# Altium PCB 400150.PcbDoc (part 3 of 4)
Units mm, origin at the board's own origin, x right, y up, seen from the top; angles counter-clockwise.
Board outline 101.6 x 63.5 mm, 4 copper layers (Top Layer, Mid-Layer 1, Mid-Layer 2, Bottom Layer), stack 1.582 mm thick; 248 components, 179 nets, 1093 pads, 875 vias.
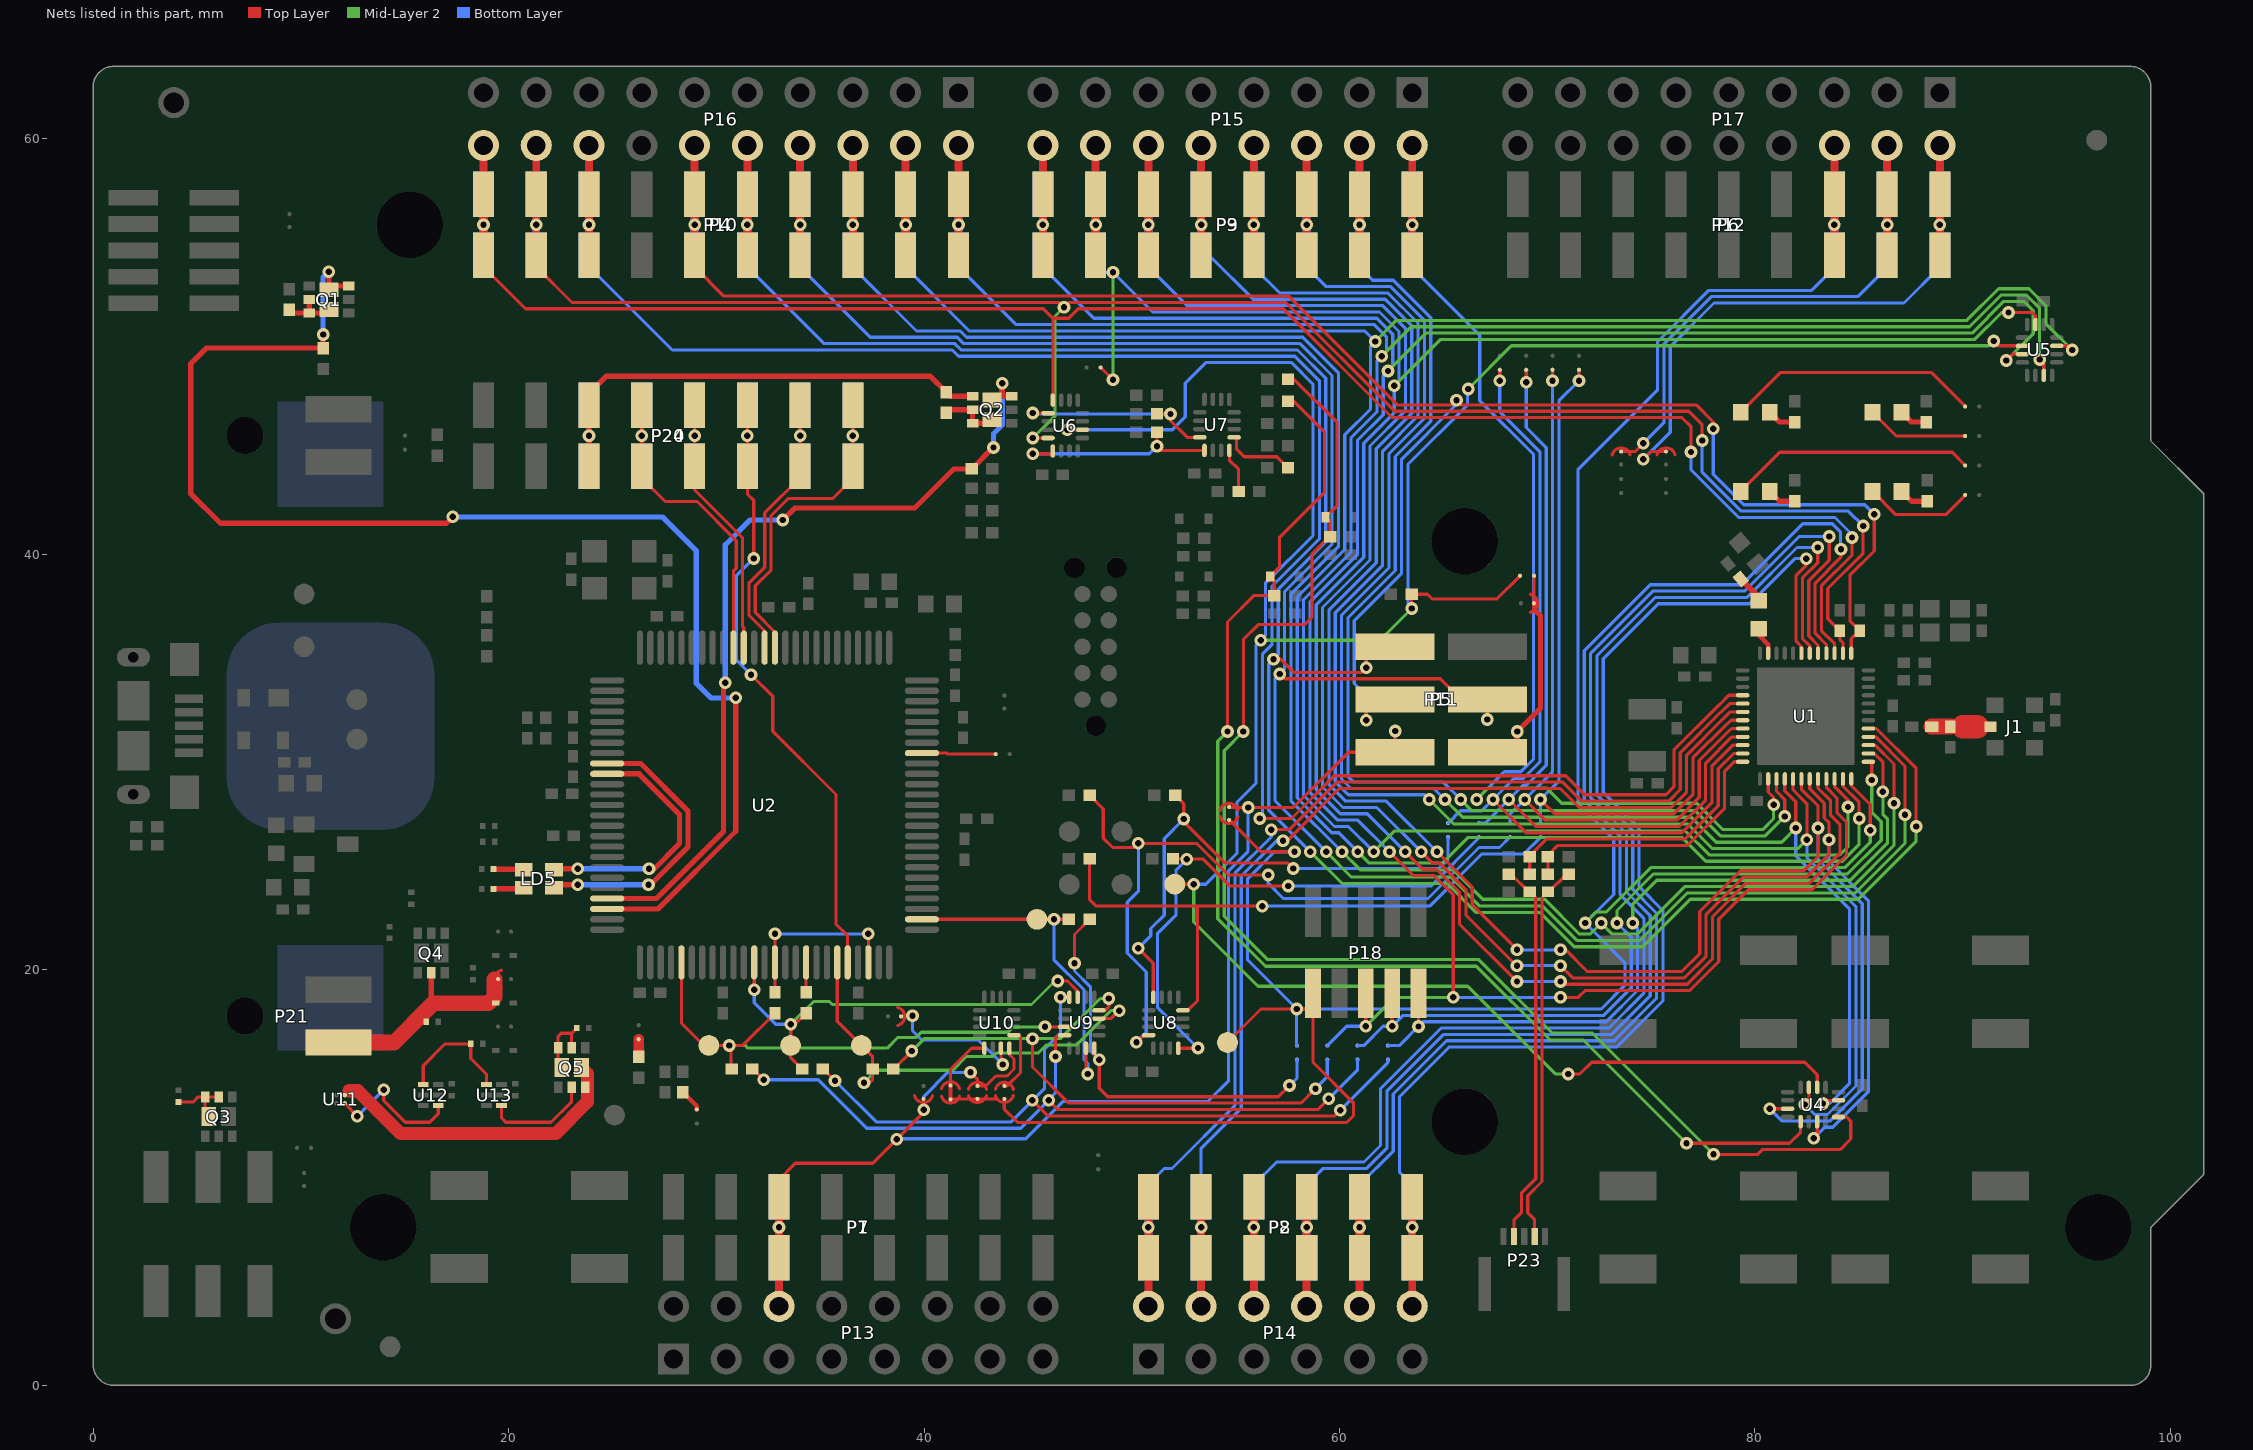
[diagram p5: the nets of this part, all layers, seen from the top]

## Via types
v1: diameter 0.61, hole 0.305, Top Layer to Bottom Layer, tented both sides, 836 vias
v2: diameter 0.61, hole 0.305, Top Layer to Bottom Layer, 23 vias
v3: diameter 0.66, hole 0.33, Top Layer to Bottom Layer, tented both sides, 16 vias

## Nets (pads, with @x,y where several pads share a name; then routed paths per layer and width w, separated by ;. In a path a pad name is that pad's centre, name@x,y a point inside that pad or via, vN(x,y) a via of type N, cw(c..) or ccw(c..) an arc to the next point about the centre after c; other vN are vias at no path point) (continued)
NetD5_1: D5.1 R35.1 R42.2 U4.9 | length 61.9
  Top Layer w0.152: v1(54.61,31.471) 54.61,36.742 55.879,38.01 R42.2@56.861,38.01 56.861,38.732 D5.1@56.661,38.932 57.107,39.378 57.107,40.8 59.274,42.967 59.274,45.891 57.804,47.361 R35.1@57.521,47.361 ; v1(76.705,11.65) 76.706,11.649 81.661,11.649 82.195,12.183 U4.9@82.195,12.688
  Mid-Layer 2 w0.152: v1(54.61,31.471) 54.143,31.004 54.143,22.458 56.436,20.165 66.589,20.165 70.137,16.618 71.739,16.618 v1(76.705,11.65) v1(76.705,11.65)
NetD6_1: D6.1 R36.1 R43.2 U4.13 | length 67.4
  Top Layer w0.152: v1(55.372,31.471) 55.372,35.897 56.089,36.613 58.313,36.613 58.682,36.982 58.682,40.03 R43.2@59.469,40.818 ; R36.1@57.521,48.428 57.804,48.428 59.884,46.348 59.884,42.339 D6.1@59.328,41.783 59.548,41.563 R43.2@59.548,40.835 ; v1(78.001,11.115) 80.128,11.115 80.357,11.344 84.1,11.344 84.608,11.852 84.608,12.716 84.411,12.913 U4.13@84.02,12.913
  Mid-Layer 2 w0.152: v1(55.372,31.471) 54.448,30.547 54.448,22.584 56.543,20.489 66.71,20.489 70.244,16.954 72.164,16.954 v1@78.001,11.118
NetD7_2: D7.2 P21.2 Q4.5 R51.1 SB12.2 | length 10.8
  Top Layer w0.254: 16.281,18.288 Q4.5@16.281,19.853
  Top Layer w0.762: P21.2@11.811,16.5 14.493,16.5 16.281,18.288 16.383,18.39 19.025,18.39 19.325,18.69 19.325,19.538
NetL2_1: L2.1 L3.2 | length 1.4
  Top Layer w0.279: L3.2@79.312,38.812 80.174,37.95 L2.1@80.174,37.768
NetL2_2: L2.2 U1.47 | length 1.4
  Top Layer w0.229: L2.2@80.174,36.418 80.174,36.117 80.635,35.656 U1.47@80.635,35.236
NetLD5_1: LD5.1 R20.1 | length 1.5
  Top Layer w0.254: R20.1@19.274,24.844 20.703,24.844 LD5.1@20.738,24.809
NetLD5_2: LD5.2 R19.1 | length 1.5
  Top Layer w0.254: R19.1@19.274,23.893 20.672,23.893 LD5.2@20.738,23.959
NetLED1_1: LED1.1 SB5.2 | length 12.3
  Top Layer w0.152: LED1.1@79.312,46.837 81.217,48.742 88.504,48.742 SB5.2@90.13,47.117
NetLED1_2: LED1.2 R1.1 | length 1.4
  Top Layer w0.254: LED1.2@80.709,46.837 81.183,46.363 R1.1@81.915,46.363
NetLED2_1: LED2.1 SB6.2 | length 4.9
  Top Layer w0.152: LED2.1@85.655,46.838 86.798,45.695 SB6.2@90.117,45.695
NetLED2_2: LED2.2 R2.1 | length 1.4
  Top Layer w0.254: LED2.2@87.052,46.838 87.527,46.363 R2.1@88.227,46.363
NetLED3_1: LED3.1 SB7.2 | length 11.9
  Top Layer w0.152: LED3.1@79.293,43.002 81.198,44.907 89.482,44.907 ; 89.495,44.907 SB7.2@90.13,44.272
NetLED3_2: LED3.2 R3.1 | length 1.4
  Top Layer w0.254: LED3.2@80.702,43.028 81.177,42.553 R3.1@81.902,42.553
NetLED4_1: LED4.1 SB8.2 | length 5.3
  Top Layer w0.152: LED4.1@85.662,43.027 86.779,41.91 89.177,41.91 ; 89.19,41.91 SB8.2@90.13,42.85
NetLED4_2: LED4.2 R4.1 | length 1.4
  Top Layer w0.254: LED4.2@87.059,43.027 87.533,42.553 R4.1@88.278,42.553
NetP5_6: P5.6 P11.6 SB18.2 SB19.1 | length 10.1
  Top Layer w0.152: SB18.2@69.367,37.577 69.367,37.988 SB19.1@69.367,38.964
  Top Layer w0.254: P5.6@68.555,30.521 v1(68.555,31.471) 69.672,32.588 69.672,37.041 69.393,37.32 69.393,37.551 69.484,37.643
  Bottom Layer w0.254: P11.6@68.555,30.521 v1(68.555,31.471)
NetQ1_5: Q1.5 Q1.6 R8.2 | length 2.7
  Top Layer w0.254: R8.2@9.449,51.763 9.599,51.613 Q1.6@10.404,51.613 ; Q1.5@10.404,52.263 Q1.6@10.404,51.613 ; Q1.6@11.354,51.788 11.179,51.613 Q1.6@10.404,51.613
NetQ2_5: Q2.5 Q2.6 R9.2 | length 3
  Top Layer w0.254: R9.2@41.072,46.81 41.216,46.954 42.332,46.954 Q2.6@42.332,46.304 ; Q2.6@42.337,46.304 43.107,46.304 Q2.6@43.282,46.479
NetQ3_5: Q3.5 Q3.6 R60.2 | length 3
  Top Layer w0.152: R60.2@4.115,13.634 4.82,13.634 5.065,13.879 Q3.5@6.045,13.879 ; Q3.6@5.395,13.874 5.395,13.104 Q3.6@5.57,12.929
NetQ5_2: Q5.2 U13.4 | length 5.2
  Top Layer w0.152: U13.4@19.667,13.47 19.667,12.864 19.873,12.657 22.045,12.657 23.038,13.65 Q5.2@23.038,14.346
NetQ5_3: Q5.3 U11.A2 | length 14.7
  Top Layer w0.635: 12.319,14.173 12.749,14.173 14.811,12.111 22.271,12.111 23.8,13.64 23.8,15.004 Q5.3@23.513,15.291
NetQ5_5: Q5.5 Q5.6 R48.2 | length 3.4
  Top Layer w0.152: Q5.6@22.563,15.291 22.388,15.466 Q5.6@22.388,16.236 22.388,16.8 22.535,16.947 23.038,16.947 ; Q5.5@23.038,16.236 23.038,16.947 ; R48.2@23.286,17.196 23.038,16.947
NetR7_1: R7.1 SB24.1 U8.16 | length 27.7
  Top Layer w0.152: R7.1@51.986,25.349 52.011,25.324 v1(52.655,25.324) 53.443,25.324 54.738,24.028 v1(57.531,24.028) ; U8.16@52.238,16.225 53.182,16.225 v1(53.188,16.231)
  Bottom Layer w0.152: v1(52.655,25.324) 52.133,24.802 52.133,22.644 51.232,21.742 51.232,18.186 v1(53.188,16.231) ; v1(57.531,24.028) 64.393,24.028 66.713,26.348 SB24.1@66.713,26.382
NetR18_1: R18.1 SB22.1 U8.4 | length 30.6
  Top Layer w0.152: R18.1@47.973,25.349 47.973,23.376 48.285,23.063 53.162,23.063 ; U8.4@52.463,18.05 52.695,18.05 53.162,18.517 53.162,23.063 ; v1(56.286,23.063) 53.162,23.063
  Bottom Layer w0.152: v1(56.286,23.063) 64.338,23.063 66.849,25.574 68.877,25.574 SB22.1@69.685,26.382
NetR32_1: R32.1 U7.1 | length 3.4
  Top Layer w0.152: U7.1@55.039,45.634 55.039,45.077 55.421,44.694 56.988,44.694 R32.1@57.521,44.161 R32.1@57.551,44.161
NetR37_1: R37.1 R38.2 U7.16 | length 2.2
  Top Layer w0.152: U7.16@54.7,45.003 54.7,44.526 55.143,44.083 R37.1@55.143,43.022
NetR49_2: R49.2 U12.1 U13.1 | length 5.9
  Top Layer w0.152: U12.1@15.893,14.47 15.893,15.385 16.942,16.434 R49.2@18.181,16.434 18.181,15.728 18.941,14.968 U13.1@18.941,14.47
NetR52_1: R52.1 SB21.1 U9.4 | length 36
  Top Layer w0.152: R52.1@31.742,15.223 31.767,15.223 v1(32.283,14.707) ; v1(45.999,13.716) 46.45,13.266 58.949,13.266 v1(59.476,13.792) ; v1(46.33,15.824) 46.33,16.706 46.473,16.85 U9.4@46.771,16.85
  Bottom Layer w0.152: v1(32.283,14.707) 34.9,14.707 37.236,12.37 44.653,12.37 v1(45.999,13.716) ; v1@45.987,13.729 46.33,14.072 v1(46.33,15.824) ; v1(59.476,13.792) 60.872,15.188 SB21.1@60.872,15.674
NetR53_1: R53.1 SB26.1 U9.8 | length 20.5
  Top Layer w0.152: v1(47.244,20.316) 47.244,21.7 R53.1@47.973,22.428 ; U9.8@48.196,16.225 48.196,15.914 v1(48.438,15.672) 48.438,14.298 48.847,13.889 57.057,13.889 v1(57.594,14.425)
  Bottom Layer w0.152: v1(47.244,20.316) 47.244,19.938 48.006,19.176 48.006,16.104 v1(48.438,15.672) ; v1(57.594,14.425) 57.953,14.785 SB26.1@57.953,15.674
NetR54_1: R54.1 SB27.1 U9.12 | length 30.3
  Top Layer w0.152: R54.1@38.524,15.223 38.543,15.223 v1(39.406,16.086) ; v1(45.224,16.686) 45.224,15.317 46.961,13.58 58.147,13.58 v1(58.841,14.275) ; U9.12@48.421,18.05 48.719,18.05 48.895,18.226 v1(48.895,18.618)
  Mid-Layer 2 w0.152: v1(39.406,16.086) 40.006,16.686 v1(45.224,16.686) 46.556,16.686 48.489,18.618 v1(48.895,18.618)
  Bottom Layer w0.152: v1(58.841,14.275) 59.412,14.846 SB27.1@59.412,15.674
NetR55_1: R55.1 SB36.1 | length 1.1
  Top Layer w0.203: R55.1@28.396,14.101 29.063,13.434 SB36.1@29.063,13.273
NetR56_1: R56.1 SB25.1 U8.8 | length 26.1
  Top Layer w0.152: v1(50.317,21.031) 51.038,20.31 U8.8@51.038,18.675 ; R56.1@52.087,28.397 52.502,27.983 v1(52.502,27.254) 52.502,27.127 54.483,25.146 57.495,25.146 v1(57.767,24.874)
  Bottom Layer w0.152: v1(50.317,21.031) 50.914,21.628 50.914,21.984 51.562,22.631 51.562,26.314 v1(52.502,27.254) ; v1(57.767,24.874) 64.777,24.874 65.227,25.324 SB25.1@65.227,26.382
NetR57_1: R57.1 SB29.1 | length 0.8
  Top Layer w0.508: R57.1@26.266,15.806 SB29.1@26.266,16.655
NetR58_1: R58.1 SB23.1 U8.12 | length 35.8
  Top Layer w0.152: R58.1@47.973,28.397 48.63,27.74 48.63,26.338 49.085,25.883 50.117,25.883 v1(50.317,26.083) 53.115,26.083 54.636,24.562 v1(56.566,24.562) ; v1(50.224,16.51) 50.564,16.85 U8.12@50.813,16.85
  Bottom Layer w0.152: v1(50.224,16.51) 50.216,16.51 50.698,16.993 50.698,19.892 49.784,20.807 49.784,23.241 50.317,23.774 v1(50.317,26.083) ; v1(56.566,24.562) 56.566,24.158 57.292,23.431 64.262,23.431 66.714,25.883 67.7,25.883 SB23.1@68.199,26.382
NetR59_1: R59.1 SB20.1 U9.16 | length 36.2
  Top Layer w0.152: R59.1@35.129,15.223 35.145,15.223 v1(35.712,14.656) ; v1(45.212,13.716) 45.974,12.954 59.752,12.954 v1(60.035,13.237) ; v1(46.567,18.679) 46.571,18.675 U9.16@46.996,18.675
  Bottom Layer w0.152: v1(35.712,14.656) 37.694,12.675 44.196,12.675 45.796,14.275 45.796,16.18 46.564,16.948 v1@46.564,18.675 ; v1(60.035,13.237) 62.331,15.533 SB20.1@62.331,15.674
NetSB31_1: SB31.1 U2.43 | length 3.6
  Top Layer w0.152: U2.43@39.899,30.43 41.097,30.43 41.148,30.378 SB31.1@43.452,30.378
NetSB41_1: SB41.1 U10.5 | length 2.8
  Top Layer w0.152: SB41.1@41.275,14.435 41.275,15.215 42.285,16.225 U10.5@42.904,16.225
NetSB44_1: SB44.1 U10.9 | length 3.1
  Top Layer w0.152: SB44.1@43.866,14.409 44,14.409 44.105,14.514 44.642,15.051 44.642,16.756 44.549,16.85 U10.9@44.329,16.85
NetSB45_1: SB45.1 U10.7 | length 7.1
  Top Layer w0.152: SB45.1@38.895,17.755 38.92,17.78 39.069,17.78 v1(39.446,17.78) ; U10.7@43.704,16.225 43.704,15.529 v1(43.79,15.443)
  Bottom Layer w0.152: v1(39.446,17.78) 39.446,17.069 39.903,16.612 42.621,16.612 v1(43.79,15.443)
NetU11_B2: U11.B2 U12.4 | length 6.8
  Top Layer w0.152: U11.B2@12.113,13.567 v1(12.725,12.954) ; v1(13.995,14.224) 13.995,13.699 15.038,12.657 16.213,12.657 16.619,13.063 U12.4@16.619,13.47
  Bottom Layer w0.152: v1(12.725,12.954) v1(13.995,14.224)
NFC1: C42.1 P23.2 R25.1 | length 18.5
  Top Layer w0.152: R25.1@68.152,24.602 68.254,24.602 69.107,23.749 C42.1@69.156,23.749 69.444,23.462 69.444,9.931 68.758,9.246 68.758,8.306 68.394,7.942 P23.2@68.394,7.163
NFC2: C43.2 P23.4 R26.1 | length 18.5
  Top Layer w0.152: P23.4@69.394,7.163 69.394,7.974 69.063,8.306 69.063,9.119 69.748,9.805 69.748,23.462 C43.2@70.036,23.749 70.077,23.749 70.93,24.602 R26.1@71.032,24.602
OB_LED1: LD5.4 U2.84 | length 13.8
  Top Layer w0.254: LD5.4@22.188,23.959 22.323,24.094 v1(23.333,24.094) ; U2.84@24.749,29.93 26.362,29.93 28.641,27.65 28.641,25.91 26.826,24.094 v1(26.736,24.094)
  Bottom Layer w0.254: v1(23.333,24.094) v1(26.736,24.094)
OB_LED2: LD5.3 U2.85 | length 12.3
  Top Layer w0.254: LD5.3@22.188,24.809 22.235,24.856 v1(23.333,24.856) ; U2.85@24.749,29.43 26.287,29.43 28.235,27.482 28.235,26.078 27.013,24.856 v1(26.762,24.856)
  Bottom Layer w0.254: v1(23.333,24.856) v1(26.762,24.856)
OB_RESET: R53.2 TP20.1 U2.27 U9.7 | length 16.6
  Top Layer w0.152: U2.27@39.899,22.43 39.901,22.428 TP20.1@45.441,22.428 v1(46.253,22.428) R53.2@46.973,22.428 ; U9.7@47.796,16.225 47.796,14.928 47.854,14.986 v1(47.879,14.986)
  Bottom Layer w0.152: v1(46.253,22.428) 46.253,20.48 47.701,19.032 47.701,15.664 47.879,15.486 v1(47.879,14.986)
OB_SWDCLK: R16.2 R52.2 TP10.1 U2.5 U9.3 | length 26.4
  Top Layer w0.152: U2.5@28.324,20.355 28.324,17.421 29.388,16.358 v1(30.632,16.358) ; R52.2@30.742,15.215 30.713,15.185 30.713,16.277 v1(30.632,16.358) ; R16.2@32.826,17.915 31.268,16.358 v1(30.632,16.358) ; v1(45.825,17.25) U9.3@46.771,17.25
  Mid-Layer 2 w0.152: v1(30.632,16.358) 31.394,16.358 31.521,16.231 38.223,16.231 38.732,16.739 39.619,16.739 39.872,16.993 44.023,16.993 44.28,17.25 v1(45.825,17.25)
OB_SWDIO: R15.2 R59.2 TP9.1 U2.12 U9.15 | length 22.8
  Top Layer w0.152: v1(31.824,19.034) U2.12@31.824,20.355 ; R59.2@34.129,15.223 33.579,15.774 TP9.1@33.579,16.358 33.588,16.366 v1(33.588,17.374) 33.783,17.374 R15.2@34.324,17.915 ; v1(46.431,19.456) 46.908,19.456 47.396,18.969 U9.15@47.396,18.675
  Mid-Layer 2 w0.152: v1(33.588,17.374) 34.68,18.466 35.451,18.466 35.588,18.329 37.64,18.329 45.176,18.329 46.304,19.456 v1(46.431,19.456)
  Bottom Layer w0.152: v1(31.824,19.034) 31.824,18.403 32.854,17.374 v1(33.588,17.374) ; v1@46.355,19.456 v1(46.431,19.456)
OB_SWO: R54.2 TP21.1 U2.20 U9.11 | length 21.7
  Top Layer w0.152: U2.20@35.824,20.355 35.824,17.516 TP21.1@36.982,16.358 37.524,15.816 37.524,14.715 37.363,14.554 v1(37.109,14.554) ; U9.11@48.421,17.65 48.993,17.65 49.403,18.059 v1(49.403,18.034)
  Mid-Layer 2 w0.152: v1(37.109,14.554) 37.719,15.164 41.377,15.164 42.037,15.824 43.314,15.824 43.482,15.993 45.508,15.993 45.886,16.371 47.334,16.371 48.997,18.034 v1(49.403,18.034)
P0.00: P6.1 P12.1 P17.2 SB4.2 | length 30.5
  Top Layer w0.152: v1(74.625,44.577) 74.996,44.948 SB4.2@75.717,44.948
  Top Layer w0.381: P6.1@88.9,54.405 v1(88.9,55.87) P6.1@88.9,57.335 P17.2@88.9,59.68
  Bottom Layer w0.152: v1(74.625,44.577) 75.921,45.872 75.921,49.987 78.029,52.095 87.173,52.095 88.9,53.823 P12.1@88.9,54.405
  Bottom Layer w0.381: P12.1@88.9,54.405 v1(88.9,55.87) P12.1@88.9,57.335
P0.01: P6.2 P12.2 P17.4 SB3.2 | length 27.5
  Top Layer w0.152: SB3.2@73.558,44.948 74.234,44.948 v1(74.625,45.339)
  Top Layer w0.381: P6.2@86.36,54.405 v1(86.36,55.87) P6.2@86.36,57.335 P17.4@86.36,59.68
  Bottom Layer w0.152: v1(74.625,45.339) 75.616,46.33 75.616,50.113 77.903,52.4 84.938,52.4 86.36,53.823 P12.2@86.36,54.405
  Bottom Layer w0.381: P12.2@86.36,54.405 v1(86.36,55.87) P12.2@86.36,57.335
P0.02: P4.8 P10.8 P16.16 U1.4 | length 97.1
  Top Layer w0.152: v1(56.159,27.28) 57.687,27.28 59.744,29.337 70.891,29.337 71.806,28.423 75.718,28.423 76.098,28.803 76.098,30.578 78.256,32.735 78.27,32.735 78.746,33.211 U1.4@79.41,33.211
  Top Layer w0.381: P4.8@23.876,54.405 v1(23.876,55.87) P4.8@23.876,57.335 P16.16@23.876,59.68
  Bottom Layer w0.152: P10.8@23.876,54.405 23.876,53.848 27.889,49.835 41.353,49.835 41.657,49.53 57.854,49.53 59.03,48.354 59.03,45.695 ; v1(56.159,27.28) 56.286,27.407 56.286,35.179 56.744,35.636 56.744,38.447 59.03,40.733 59.03,46.255
  Bottom Layer w0.381: P10.8@23.876,53.838 v1(23.876,55.87) P10.8@23.876,57.335
P0.03: P2.1 P8.1 P14.2 U1.5 | length 55.5
  Top Layer w0.152: v1(56.718,26.746) 57.584,26.746 59.87,29.032 70.745,29.032 71.659,28.118 75.845,28.118 76.403,28.676 76.403,30.452 78.382,32.43 78.397,32.43 78.778,32.811 U1.5@79.41,32.811
  Top Layer w0.381: P14.2@50.8,3.8 P2.1@50.8,6.145 v1(50.8,7.61) P2.1@50.8,9.075
  Bottom Layer w0.152: P8.1@50.8,9.667 51.568,10.435 51.939,10.435 54.966,13.461 54.966,24.638 56.718,26.391 v1(56.718,26.746)
  Bottom Layer w0.381: P8.1@50.8,6.145 v1(50.8,7.61) P8.1@50.8,9.667
P0.04: P2.2 P8.2 P14.4 U1.6 | length 53.7
  Top Layer w0.152: v1(57.277,26.213) 57.482,26.213 59.996,28.727 70.618,28.727 71.532,27.813 75.972,27.813 76.708,28.549 76.708,30.325 78.508,32.126 78.524,32.126 78.809,32.411 U1.6@79.41,32.411
  Top Layer w0.381: P14.4@53.34,3.8 P2.2@53.34,6.145 v1(53.34,7.61) P2.2@53.34,9.075
  Bottom Layer w0.152: P8.2@53.34,9.075 53.34,11.405 55.27,13.335 55.27,24.512 56.971,26.213 v1(57.277,26.213)
  Bottom Layer w0.381: P8.2@53.34,6.145 v1(53.34,7.61) P8.2@53.34,9.075
P0.05: SB13.2 SB22.2 U1.7 | length 35.5
  Top Layer w0.152: v1(69.672,28.194) 70.358,27.508 76.099,27.508 77.013,28.422 77.013,30.199 78.635,31.821 78.654,31.821 78.844,32.011 U1.7@79.41,32.011 ; v1(71.526,48.346) SB13.2@71.526,48.88
  Bottom Layer w0.152: SB22.2@69.685,27.058 69.672,27.071 v1(69.672,28.194) 70.561,29.083 70.561,47.381 v1(71.526,48.346)
P0.06: SB14.2 SB23.2 U1.8 | length 36.5
  Top Layer w0.152: v1(68.91,28.194) 69.901,27.203 76.226,27.203 77.318,28.295 77.318,30.073 78.761,31.516 78.78,31.516 78.875,31.611 U1.8@79.41,31.611 ; v1(70.256,48.346) SB14.2@70.256,48.88
  Bottom Layer w0.152: SB23.2@68.199,27.058 68.199,27.483 v1(68.91,28.194) 70.256,29.54 v1(70.256,48.346)
P0.07: SB15.2 SB24.2 U1.9 | length 38.5
  Top Layer w0.152: v1(68.148,28.194) 69.444,26.899 76.352,26.899 77.622,28.169 77.622,29.947 78.887,31.211 U1.9@79.41,31.211 ; v1(68.986,48.285) SB15.2@68.986,48.88
  Bottom Layer w0.152: SB24.2@66.713,27.058 67.012,27.058 v1(68.148,28.194) 68.85,28.896 69.008,28.896 69.952,29.839 69.952,45.136 68.986,46.101 v1(68.986,48.285)
P0.08: SB16.2 SB25.2 U1.10 | length 40.8
  Top Layer w0.152: v1(67.386,28.194) 68.986,26.594 76.48,26.594 77.927,28.041 77.927,29.801 78.937,30.811 U1.10@79.41,30.811 ; v1(67.716,48.346) SB16.2@67.716,48.88
  Bottom Layer w0.152: SB25.2@65.227,27.058 65.82,27.65 66.843,27.65 v1(67.386,28.194) 68.403,29.211 68.855,29.211 69.647,30.003 69.647,44.933 67.716,46.863 v1(67.716,48.346)
P0.09/NFC1: R25.2 R27.2 U1.11 | length 14.2
  Top Layer w0.152: R25.2@69.156,24.613 69.156,25.492 69.953,26.289 76.624,26.289 78.232,27.897 78.232,29.675 78.968,30.411 U1.11@79.41,30.411
P0.10/NFC2: R26.2 R28.2 U1.12 | length 13.2
  Top Layer w0.152: R26.2@70.036,24.613 70.036,25.506 70.514,25.984 76.75,25.984 78.537,27.771 78.537,29.549 78.999,30.011 U1.12@79.41,30.011
P0.11: P3.1 P9.1 P15.2 U1.14 | length 56
  Top Layer w0.152: U1.14@80.635,29.186 80.635,28.556 80.899,28.292 v1(80.899,27.941)
  Top Layer w0.381: P3.1@63.5,54.405 v1(63.5,55.87) P3.1@63.5,57.335 P15.2@63.5,59.68
  Mid-Layer 2 w0.152: v1(66.599,28.194) 67.143,28.738 69.98,28.738 70.701,28.017 77.19,28.017 78.461,26.746 80.366,26.746 80.899,27.279 v1(80.899,27.941)
  Bottom Layer w0.152: P9.1@63.5,53.797 66.751,50.546 66.751,47.392 69.342,44.801 69.342,30.144 68.731,29.533 67.938,29.533 v1(66.599,28.194)
  Bottom Layer w0.381: P9.1@63.5,53.797 v1(63.5,55.87) P9.1@63.5,57.335
P0.12: P3.2 P9.2 P15.4 U1.15 | length 62.1
  Top Layer w0.152: U1.15@81.035,29.186 81.035,28.588 81.432,28.191 v1(81.432,27.381)
  Top Layer w0.381: P3.2@60.96,54.405 v1(60.96,55.87) P3.2@60.96,57.335 P15.4@60.96,59.68
  Mid-Layer 2 w0.152: v1(65.837,28.194) 66.372,27.659 77.116,27.659 78.334,26.441 80.493,26.441 v1(81.432,27.381)
  Bottom Layer w0.152: v1(65.837,28.194) 64.999,29.032 60.681,29.032 60.401,29.312 60.401,36.932 62.687,39.218 62.687,44.708 64.389,46.41 64.389,51.383 62.584,53.188 61.595,53.188 P9.2@60.96,53.823 ; P9.2@60.96,53.823 60.96,54.405 P9.2@60.96,53.823
  Bottom Layer w0.381: P9.2@60.96,54.405 v1(60.96,55.87) P9.2@60.96,57.335
P0.13: P3.3 P9.3 P15.6 U1.16 U4.15 | length 81.1
  Top Layer w0.152: U1.16@81.435,29.186 81.435,28.62 81.966,28.089 v1(81.966,26.822) ; v1(83.261,13.564) 83.41,13.713 U4.15@84.02,13.713
  Top Layer w0.381: P3.3@58.42,54.405 v1(58.42,55.87) P3.3@58.42,57.335 P15.6@58.42,59.68
  Mid-Layer 2 w0.152: v1(65.075,28.194) 65.927,27.342 76.931,27.342 78.136,26.137 81.28,26.137 v1(81.966,26.822)
  Bottom Layer w0.152: P9.3@58.42,54.405 58.42,53.823 59.36,52.883 62.458,52.883 64.084,51.256 64.084,46.536 62.382,44.834 62.382,39.344 60.096,37.058 60.096,29.185 60.554,28.727 64.541,28.727 v1(65.075,28.194) ; v1(81.966,26.822) 81.966,25.497 84.557,22.906 84.557,14.529 83.591,13.564 v1(83.261,13.564)
  Bottom Layer w0.381: P9.3@58.42,54.405 v1(58.42,55.87) P9.3@58.42,57.335
P0.14: P3.4 P9.4 P15.8 U1.17 U4.3 | length 85.9
  Top Layer w0.152: U1.17@81.835,29.186 81.835,28.652 82.499,27.987 v1(82.499,26.264) ; v1(82.389,13.513) 82.595,13.719 U4.3@82.595,14.338
  Top Layer w0.381: P3.4@55.88,54.405 v1(55.88,55.87) P3.4@55.88,57.335 P15.8@55.88,59.68
  Mid-Layer 2 w0.152: v1(64.313,28.194) 65.491,27.016 76.768,27.016 77.953,25.832 82.067,25.832 v1(82.499,26.264)
  Bottom Layer w0.152: P9.4@55.88,54.405 55.88,53.823 57.125,52.578 62.332,52.578 63.779,51.13 63.779,46.662 62.078,44.961 62.078,39.47 59.792,37.184 59.792,29.058 60.427,28.423 64.084,28.423 v1(64.313,28.194) ; v1(82.389,13.513) 82.872,13.03 83.49,13.03 84.861,14.402 84.861,23.041 82.499,25.403 v1(82.499,26.264)
  Bottom Layer w0.381: P9.4@55.88,54.405 v1(55.88,55.87) P9.4@55.88,57.335
P0.15: P3.5 P9.5 P15.10 U1.18 U4.7 | length 98.4
  Top Layer w0.152: v1(64.694,25.679) 66.389,23.984 66.389,23.122 v1(68.547,20.964) ; v1@70.637,20.955 70.883,20.955 71.924,19.914 76.479,19.914 77.343,20.777 77.343,22.807 79.301,24.765 82.347,24.765 83.033,25.451 v1(83.033,26.822) 83.033,27.886 82.235,28.684 U1.18@82.235,29.186 ; v1@80.716,13.313 U4.7@81.57,13.313
  Top Layer w0.381: P3.5@53.34,54.405 v1(53.34,55.87) P3.5@53.34,57.335 P15.10@53.34,59.68
  Bottom Layer w0.152: P9.5@53.34,54.405 53.712,54.405 55.844,52.273 62.205,52.273 63.475,51.004 63.475,46.789 61.773,45.087 61.773,39.596 59.487,37.31 59.487,28.924 60.293,28.118 62.255,28.118 v1(64.694,25.679) ; v1(68.547,20.964) 68.557,20.955 v1@70.637,20.955 ; v1(80.713,13.31) 81.297,12.725 83.617,12.725 85.166,14.275 85.166,23.175 83.033,25.308 v1(83.033,26.822)
  Bottom Layer w0.381: P9.5@53.34,54.405 v1(53.34,55.87) P9.5@53.34,57.335
  other v1: 70.637,20.964
P0.16: P3.6 P9.6 P15.12 U1.19 U4.11 | length 100
  Top Layer w0.152: v1(63.932,25.679) 64.465,25.146 64.796,25.146 66.084,23.858 66.084,22.636 68.522,20.198 v1(68.547,20.198) ; v1@70.637,20.193 71.221,19.609 76.606,19.609 77.648,20.651 77.648,22.681 79.427,24.46 82.473,24.46 83.566,25.553 v1(83.566,26.264) 83.566,27.076 83.337,27.305 83.337,28.012 82.635,28.715 U1.19@82.635,29.186 ; v1(82.821,11.887) 82.995,12.062 U4.11@82.995,12.688
  Top Layer w0.381: P3.6@50.8,54.405 v1(50.8,55.87) P3.6@50.8,57.335 P15.12@50.8,59.68
  Bottom Layer w0.152: P9.6@50.8,54.405 50.8,53.838 52.669,51.968 62.079,51.968 63.17,50.878 63.17,46.915 61.468,45.213 61.468,39.723 59.182,37.437 59.182,28.798 60.167,27.813 61.798,27.813 v1(63.932,25.679) ; v1(68.547,20.198) v1(70.637,20.198) ; v1(82.821,11.887) 83.354,12.421 83.744,12.421 85.471,14.148 85.471,23.304 83.566,25.209 v1(83.566,26.264)
  Bottom Layer w0.381: P9.6@50.8,54.405 v1(50.8,55.87) P9.6@50.8,57.335
P0.17: P3.7 P9.7 P15.14 SB30.1 U1.20 U5.15 | length 125
  Top Layer w0.152: SB30.1@48.502,48.991 48.512,48.991 v1(49.097,48.407) ; v1(63.17,25.679) 64.008,24.841 64.668,24.841 65.779,23.731 65.779,22.2 v1(68.547,19.431) ; v1(70.637,19.431) 70.764,19.304 76.732,19.304 77.953,20.525 77.953,22.554 79.554,24.155 82.618,24.155 84.099,25.637 84.099,26.976 83.642,27.433 83.642,28.138 83.035,28.746 U1.20@83.035,29.186 ; v1(92.201,51.638) 93.345,51.638 93.501,51.483 U5.15@93.501,51.06
  Top Layer w0.381: P3.7@48.26,54.405 P3.7@48.26,57.335 P15.14@48.26,59.68
  Mid-Layer 2 w0.152: v1(49.097,48.407) v1(49.098,53.569) ; v1(62.636,48.108) 64.872,50.343 90.576,50.343 91.872,51.638 v1(92.201,51.638)
  Bottom Layer w0.152: P9.7@48.26,54.405 48.26,53.797 48.489,53.569 v1(49.098,53.569) 51.003,51.664 61.924,51.664 62.865,50.722 62.865,48.336 v1(62.636,48.108) 62.636,46.82 61.163,45.347 61.163,39.849 58.877,37.563 58.877,28.671 60.04,27.508 61.341,27.508 v1(63.17,25.679) ; v1(68.547,19.431) v1(70.637,19.431)
  Bottom Layer w0.381: P9.7@48.26,54.405 v1(48.26,55.87) P9.7@48.26,57.335
P0.18: P3.8 P9.8 P15.16 P18.6 SB27.2 U1.21 U5.3 | length 136.4
  Top Layer w0.152: v1(61.265,17.278) P18.6@61.265,18.872 ; v1@62.4,25.679 v1(62.408,25.679) 63.551,24.536 64.541,24.536 65.474,23.604 v1(65.474,18.669) ; v1(70.637,18.669) 71.501,18.669 71.831,18.999 76.858,18.999 78.257,20.398 78.257,22.428 79.68,23.851 82.744,23.851 84.404,25.511 84.404,27.102 83.947,27.559 83.947,28.265 83.435,28.777 U1.21@83.435,29.186 ; v1(92.1,49.327) 92.408,49.635 U5.3@92.876,49.635
  Top Layer w0.381: P3.8@45.72,54.405 v1(45.72,55.87) P3.8@45.72,57.335 P15.16@45.72,59.68
  Mid-Layer 2 w0.152: v1(61.265,17.278) 62.656,18.669 v1(65.474,18.669) ; v1(62.332,48.819) 64.16,50.648 90.449,50.648 91.975,52.173 92.938,52.173 93.396,51.716 93.396,50.622 v1(92.1,49.327)
  Bottom Layer w0.152: P9.8@45.72,54.405 45.72,53.812 48.174,51.359 61.797,51.359 62.56,50.596 62.56,49.047 v1(62.332,48.819) 62.103,48.59 62.103,46.719 60.858,45.474 60.858,39.975 58.572,37.689 58.572,28.545 59.914,27.203 60.884,27.203 v1(62.408,25.679) ; SB27.2@59.412,16.35 60.34,17.278 v1(61.265,17.278) ; v1(65.474,18.669) v1@70.383,18.669
  Bottom Layer w0.381: P9.8@45.72,54.405 v1(45.72,55.87) P9.8@45.72,57.335
P0.19: P4.1 P10.1 P16.2 U1.22 U5.7 | length 123.5
  Top Layer w0.152: P4.1@41.656,53.842 P4.1@41.656,54.405 ; U1.22@83.835,29.186 83.835,28.808 84.48,28.162 v1(84.48,27.838) ; v1(93.701,49.378) 93.901,49.178 U5.7@93.901,48.61
  Top Layer w0.381: P4.1@41.656,54.405 v1(41.656,55.87) P4.1@41.656,57.335 P16.2@41.656,59.68
  Mid-Layer 2 w0.152: v1(61.646,25.679) 62.652,26.686 76.632,26.686 77.791,25.527 84.074,25.527 84.48,25.933 v1(84.48,27.838) ; v1(62.027,49.53) 63.449,50.952 90.323,50.952 91.849,52.478 93.065,52.478 93.701,51.842 v1(93.701,49.378)
  Bottom Layer w0.152: P10.1@41.656,54.405 41.656,53.842 44.444,51.054 61.671,51.054 62.255,50.47 62.255,49.759 v1(62.027,49.53) 61.798,49.301 61.798,46.846 60.554,45.601 60.554,40.101 58.268,37.815 58.268,28.393 59.762,26.899 60.427,26.899 v1(61.646,25.679)
  Bottom Layer w0.381: P10.1@41.656,54.405 v1(41.656,55.87) P10.1@41.656,57.335
P0.20: P4.2 P10.2 P16.4 U1.23 U5.11 | length 127.3
  Top Layer w0.152: P4.2@39.116,53.812 P4.2@39.116,54.405 ; U1.23@84.235,29.186 84.235,28.839 85.014,28.06 v1(85.014,27.28) ; U5.11@94.526,50.035 95.075,50.035 v1(95.275,49.835)
  Top Layer w0.381: P4.2@39.116,54.405 v1(39.116,55.87) P4.2@39.116,57.335 P16.4@39.116,59.68
  Mid-Layer 2 w0.152: v1(60.884,25.679) 61.428,25.135 64.948,25.135 66.174,26.361 76.5,26.361 77.638,25.222 84.2,25.222 85.014,26.036 v1(85.014,27.28) ; v1(61.722,50.241) 62.738,51.257 90.197,51.257 91.723,52.783 93.191,52.783 94.005,51.968 94.005,51.105 v1(95.275,49.835)
  Bottom Layer w0.152: P10.2@39.116,54.405 39.116,53.812 42.179,50.749 61.214,50.749 v1(61.722,50.241) 61.493,50.013 61.493,46.99 60.249,45.745 60.249,40.228 57.963,37.942 57.963,28.266 59.635,26.594 59.969,26.594 v1(60.884,25.679)
  Bottom Layer w0.381: P10.2@39.116,54.405 v1(39.116,55.87) P10.2@39.116,57.335
P0.21: P6.3 P12.3 P17.6 P18.10 SB17.2 SB26.2 SB41.2 SB43.2 SB44.2 TP11.1 U1.24 | length 135.5
  Top Layer w0.152: SB41.2@41.275,13.785 SB43.2@42.57,13.785 43.513,13.785 ; SB44.2@43.866,13.785 43.866,13.61 43.866,13.291 44.511,12.646 60.354,12.646 60.667,12.958 60.667,13.601 58.725,15.543 P18.10@58.725,18.872 ; TP11.1@54.61,16.5 56.22,18.11 v1(57.937,18.11) P18.10@58.725,18.11 ; SB17.2@54.686,27.214 56.22,25.679 v1(57.836,25.679) ; U1.24@84.635,29.186 84.635,28.87 85.547,27.958 v1(85.547,26.721)
  Top Layer w0.381: P6.3@83.82,54.405 v1(83.82,55.87) P6.3@83.82,57.335 P17.6@83.82,59.68
  Mid-Layer 2 w0.152: v1(71.831,22.25) 72.365,22.784 72.855,22.784 74.989,24.917 84.328,24.917 85.547,26.137 v1(85.547,26.721)
  Bottom Layer w0.152: v1(57.836,25.679) 56.871,25.679 55.575,24.384 55.575,20.472 v1(57.937,18.11) ; SB26.2@57.953,16.35 57.937,16.366 v1(57.937,18.11) ; P12.3@83.82,54.405 83.82,53.797 82.728,52.705 77.774,52.705 75.311,50.242 75.311,47.912 71.476,44.077 71.476,28.016 73.203,26.289 73.203,23.622 v1(71.831,22.25) 73.736,20.345 73.736,19.252 72.594,18.11 v1(57.937,18.11)
  Bottom Layer w0.381: P12.3@83.82,54.405 v1(83.82,55.87) P12.3@83.82,57.335
P0.22: P4.3 P10.3 P16.6 U1.27 | length 96
  Top Layer w0.152: U1.27@85.46,30.811 85.784,30.811 86.69,29.905 v1(86.69,28.017)
  Top Layer w0.381: P4.3@36.576,53.812 v1(36.576,55.87) P4.3@36.576,57.335 P16.6@36.576,59.68
  Mid-Layer 2 w0.152: v1(60.122,25.679) 60.995,24.806 65.473,24.806 66.886,23.393 69.875,23.393 71.552,21.717 72.06,21.717 v1(72.593,22.25) 73.127,21.717 74.339,21.717 76.625,24.003 84.709,24.003 86.69,25.984 v1(86.69,28.017)
  Bottom Layer w0.152: P10.3@36.576,54.405 36.576,53.812 39.639,50.749 41.742,50.749 42.047,50.444 58.233,50.444 59.944,48.733 59.944,45.695 ; 59.944,45.877 59.944,40.354 57.658,38.068 57.658,28.14 v1(60.122,25.679)
  Bottom Layer w0.381: P10.3@36.576,54.405 v1(36.576,55.87) P10.3@36.576,57.335
P0.23: P4.4 P5.4 P10.4 P11.4 P16.8 U1.28 | length 112.9
  Top Layer w0.152: v1(57.125,34.239) 57.353,34.011 64.846,34.011 65.847,33.01 P5.4@67.12,33.01 v1(67.12,32.045) ; U1.28@85.46,31.211 85.815,31.211 87.224,29.803 v1(87.224,27.458)
  Top Layer w0.381: P4.4@34.036,53.812 v1(34.036,55.87) P4.4@34.036,57.335 P16.8@34.036,59.68
  Mid-Layer 2 w0.152: v1(59.36,25.679) 60.572,24.467 65.342,24.467 66.746,23.063 69.775,23.063 71.426,21.412 74.465,21.412 76.751,23.698 84.837,23.698 87.224,26.085 v1(87.224,27.458)
  Bottom Layer w0.152: P10.4@34.036,54.405 34.036,53.812 37.404,50.444 41.605,50.444 41.91,50.14 58.106,50.14 59.639,48.607 59.639,40.48 57.353,38.194 57.353,34.468 v1(57.125,34.239) 56.896,34.011 56.896,28.143 v1(59.36,25.679) ; v1(67.12,32.045) 67.12,33.01 P11.4@67.722,33.01
  Bottom Layer w0.381: P10.4@34.036,54.405 v1(34.036,55.87) P10.4@34.036,57.335
P0.24: P4.5 P5.1 P10.5 P11.1 P16.10 U1.29 | length 111.2
  Top Layer w0.152: v1(56.82,34.95) 57.171,34.95 57.806,34.315 61.062,34.315 v1(61.29,34.544) P5.1@61.29,35.535 ; U1.29@85.46,31.611 85.846,31.611 87.757,29.7 v1(87.757,26.899)
  Top Layer w0.381: P4.5@31.496,53.838 v1(31.496,55.87) P4.5@31.496,57.335 P16.10@31.496,59.68
  Mid-Layer 2 w0.152: v1(58.598,25.679) 60.12,24.157 65.182,24.157 66.591,22.748 69.658,22.748 71.299,21.107 74.592,21.107 76.878,23.393 84.963,23.393 87.757,26.187 v1(87.757,26.899)
  Bottom Layer w0.152: P10.5@31.496,54.405 31.496,53.838 35.194,50.14 41.479,50.14 41.784,49.835 57.98,49.835 59.334,48.48 59.334,45.695 ; v1@56.82,34.925 v1(56.82,34.95) ; v1(58.598,25.679) 56.591,27.686 56.591,34.722 v1(56.82,34.95) ; 59.334,46.129 59.334,40.606 57.048,38.32 57.048,35.179 v1(56.82,34.95) ; v1(61.29,34.544) P11.1@61.29,35.56
  Bottom Layer w0.381: P10.5@31.496,54.405 v1(31.496,55.87) P10.5@31.496,57.335
P0.25: C52.1 P4.6 P5.3 P10.6 P11.3 P16.12 U1.37 | length 99.6
  Top Layer w0.152: P4.6@28.956,53.838 30.368,52.426 57.549,52.426 62.781,47.193 65.405,47.193 v1(65.634,47.422) 65.862,47.193 77.165,47.193 77.99,46.369 v1(77.99,46.038) ; v1(61.29,32.004) P5.3@61.29,32.969 ; U1.37@84.635,35.236 84.635,35.936 C52.1@85.029,36.33 ; C52.1@85.051,36.309 C52.1@85.029,36.33 ; v1(85.737,41.924) 85.737,40.155 84.568,38.986 84.568,36.791 C52.1@85.029,36.33
  Top Layer w0.381: P4.6@28.956,53.838 v1(28.956,55.87) P4.6@28.956,57.335 P16.12@28.956,59.68
  Bottom Layer w0.152: v1(61.29,32.004) P11.3@61.29,32.969 ; P11.3@61.473,33.01 P11.3@62.072,33.01 61.478,33.01 60.706,33.782 60.706,36.805 62.992,39.091 62.992,44.574 65.634,47.215 v1(65.634,47.422) ; v1(77.99,46.038) 77.99,43.853 79.462,42.381 85.28,42.381 v1(85.737,41.924)
  Bottom Layer w0.381: P10.6@28.956,54.405 v1(28.956,55.87) P10.6@28.956,57.335
P0.26: C53.1 P4.9 P10.9 P16.18 U1.38 U6.12 | length 94.1
  Top Layer w0.152: P4.9@21.336,53.838 23.053,52.121 46.507,52.121 v1(46.736,51.892) 46.965,52.121 57.421,52.121 62.654,46.888 76.81,46.888 77.456,46.242 v1(77.456,45.48) ; v1(45.241,45.597) U6.12@45.978,45.597 ; U1.38@84.235,35.236 84.235,35.745 84.086,35.894 C53.1@84.086,36.309 83.502,36.893 83.502,38.35 85.203,40.052 v1(85.203,41.365)
  Top Layer w0.381: P4.9@21.336,53.838 v1(21.336,55.87) P4.9@21.336,57.335 P16.18@21.336,59.68
  Mid-Layer 2 w0.152: v1(45.241,45.597) 46.312,46.668 46.312,51.468 v1(46.736,51.892)
  Bottom Layer w0.152: v1(77.456,45.48) 77.456,43.956 79.336,42.076 84.492,42.076 v1(85.203,41.365)
  Bottom Layer w0.381: P10.9@21.336,54.405 v1(21.336,55.87) P10.9@21.336,57.335
P0.27: P4.10 P10.10 P16.20 U1.39 U6.8 | length 92.1
  Top Layer w0.152: P4.10@18.796,53.838 20.818,51.816 45.745,51.816 46.203,51.359 ; U6.8@46.203,47.422 46.203,51.359 ; v1(76.923,44.921) 76.923,46.14 76.479,46.584 62.527,46.584 57.295,51.816 47.422,51.816 46.965,51.359 46.203,51.359 ; U1.39@83.835,35.236 83.835,35.686 83.197,36.324 83.197,38.477 84.67,39.95 v1(84.67,40.806)
  Top Layer w0.381: P4.10@18.796,53.838 v1(18.796,55.87) P4.10@18.796,57.335 P16.20@18.796,59.68
  Bottom Layer w0.152: v1(76.923,44.921) 76.923,44.058 79.21,41.771 83.849,41.771 84.67,40.95 v1(84.67,40.806)
  Bottom Layer w0.381: P10.10@18.796,54.405 v1(18.796,55.87) P10.10@18.796,57.335
P0.28: P2.3 P8.3 P14.6 U1.40 | length 72.3
  Top Layer w0.152: U1.40@83.435,35.236 83.435,35.655 82.892,36.198 82.892,38.603 84.137,39.848 v1(84.137,40.247)
  Top Layer w0.381: P14.6@55.88,3.8 P2.3@55.88,6.145 v1(55.88,7.61) P2.3@55.88,9.075
  Bottom Layer w0.152: P8.3@55.88,9.075 55.88,9.652 56.972,10.744 61.18,10.744 61.976,11.54 61.976,14.275 64.897,17.196 72.973,17.196 74.651,18.874 74.651,22.475 73.508,23.618 73.508,26.435 71.78,28.163 71.78,35.357 74.955,38.532 79.367,38.532 82.302,41.466 83.723,41.466 84.111,41.078 84.111,40.273 v1(84.137,40.247)
  Bottom Layer w0.381: P8.3@55.88,6.145 v1(55.88,7.61) P8.3@55.88,9.075
P0.29: P2.4 P8.4 P14.8 U1.41 | length 68.3
  Top Layer w0.152: U1.41@83.035,35.236 83.035,35.624 82.587,36.072 82.587,38.729 83.578,39.72 v1@83.578,40.781
  Top Layer w0.381: P14.8@58.42,3.8 P2.4@58.42,6.145 v1(58.42,7.61) P2.4@58.42,9.075
  Bottom Layer w0.152: P8.4@58.42,9.642 59.218,10.439 61.307,10.439 62.281,11.413 62.281,14.148 65.024,16.891 73.099,16.891 74.955,18.747 74.955,22.601 73.812,23.744 73.812,26.562 72.085,28.289 72.085,35.228 75.084,38.227 79.494,38.227 82.123,40.857 v1(83.578,40.857)
  Bottom Layer w0.381: P8.4@58.42,6.145 v1(58.42,7.61) P8.4@58.42,9.642
P0.30: P2.5 P8.5 P14.10 U1.42 | length 64.4
  Top Layer w0.152: U1.42@82.635,35.236 82.635,35.593 82.282,35.946 82.282,38.856 83.019,39.592 v1(83.019,40.323) v1@83.019,40.349
  Top Layer w0.381: P14.10@60.96,3.8 P2.5@60.96,6.145 v1(60.96,7.61) P2.5@60.96,9.075
  Bottom Layer w0.152: P8.5@60.96,9.642 62.586,11.267 62.586,14.022 65.15,16.586 73.225,16.586 75.26,18.621 75.26,22.727 74.117,23.87 74.117,26.688 72.39,28.415 72.39,35.102 75.21,37.922 79.62,37.922 82.021,40.323 v1(83.019,40.323)
  Bottom Layer w0.381: P8.5@60.96,6.145 v1(60.96,7.61) P8.5@60.96,9.642
P0.31: P2.6 P8.6 P14.12 U1.43 | length 62.1
  Top Layer w0.152: U1.43@82.235,35.236 82.235,35.562 81.978,35.819 81.978,38.982 82.46,39.464 v1(82.46,39.79)
  Top Layer w0.381: P14.12@63.5,3.8 P2.6@63.5,6.145 v1(63.5,7.61) P2.6@63.5,9.075
  Bottom Layer w0.152: P8.6@63.5,9.075 63.5,9.642 62.89,10.251 62.89,13.895 65.277,16.281 73.351,16.281 75.565,18.495 75.565,22.853 74.422,23.996 74.422,26.814 72.695,28.541 72.695,34.976 75.336,37.617 79.746,37.617 81.919,39.79 v1(82.46,39.79)
  Bottom Layer w0.381: P8.6@63.5,6.145 v1(63.5,7.61) P8.6@63.5,9.075
PB5: Q2.3 R10.2 U2.97 | length 40.6
  Top Layer w0.254: U2.97@24.749,23.43 27.123,23.43 30.353,26.66 30.353,33.746 v1(30.429,33.823) ; v1(33.198,41.646) 33.782,42.23 39.555,42.23 41.434,44.11 R10.2@42.295,44.11 43.322,45.137 v1(43.345,45.137) ; Q2.3@43.282,47.429 43.457,47.604 43.767,47.604 ; v1(43.764,48.236) 43.764,47.608 43.767,47.604 ; Q2.3@44.227,47.672 Q2.3@44.227,47.604 43.767,47.604
  Bottom Layer w0.254: v1(30.429,33.823) 30.429,40.452 31.623,41.646 v1(33.198,41.646) ; v1(43.345,45.137) 43.345,45.803 43.764,46.221 v1(43.764,48.236)
PB6: Q1.3 R11.2 U2.98 | length 67
  Top Layer w0.254: v1(11.074,50.58) R11.2@11.074,49.926 ; v1(11.354,53.594) Q1.3@11.354,52.738 11.529,52.913 Q1.3@12.304,52.913 ; v1(17.323,41.798) 17.018,41.493 6.139,41.493 4.699,42.933 4.699,49.164 5.461,49.926 R11.2@11.074,49.926 ; U2.98@24.749,22.93 27.198,22.93 30.937,26.669 v1(30.937,33.086) ; R11.2@11.074,49.926 R11.2@11.074,49.918 11.082,49.926 R11.2@11.074,49.926
  Bottom Layer w0.254: v1(11.074,50.58) 11.074,53.315 v1(11.354,53.594) ; v1(17.323,41.798) 27.407,41.798 29.032,40.173 29.032,33.797 29.743,33.086 v1@30.912,33.086
RESET_PIN: P1.3 P5.5 P7.3 P11.5 P13.6 SB17.1 SB42.2 SB43.1 U10.8 | length 67.2
  Top Layer w0.152: P1.3@33.02,9.075 33.02,9.896 33.807,10.683 37.531,10.683 v1(38.684,11.836) ; v1@38.659,11.836 v1(38.684,11.836) ; SB42.2@39.98,13.785 39.98,13.61 v1(39.98,13.259) 39.98,13.132 v1(38.684,11.836) ; v1(42.24,15.062) 42.57,14.732 42.57,14.584 SB43.1@42.57,14.409 42.924,14.409 42.984,14.409 43.461,14.886 43.998,14.886 44.334,15.223 44.334,15.704 44.104,15.934 U10.8@44.104,16.225 ; SB17.1@54.712,27.813 55.057,27.813 v1(55.601,27.813) 57.782,27.813 60.439,30.47 P5.5@62.675,30.47 ; P5.5@62.679,30.475 v1(62.679,31.496)
  Top Layer w0.381: P13.6@33.02,3.8 P1.3@33.02,6.145 v1(33.02,7.61) P1.3@33.02,9.075
  Bottom Layer w0.152: v1(38.684,11.836) 38.71,11.862 44.9,11.862 46.703,13.665 53.67,13.665 54.661,14.656 54.661,24.773 55.601,25.713 v1(55.601,27.813) ; v1(39.98,13.259) 39.98,13.894 41.148,15.062 v1(42.24,15.062) ; P11.5@62.679,30.47 v1(62.679,31.496)
  Bottom Layer w0.381: P7.3@33.02,6.145 v1(33.02,7.61) P7.3@33.02,9.075
RF: C13.1 J1.1 L1.2 | length 1.6
  Top Layer w0.508: C13.1@89.405,31.703 C13.1@89.408,31.706
  Top Layer w0.762: L1.2@88.498,31.703 C13.1@89.405,31.703
  Top Layer w1.143: 90.014,31.703 90.7,31.703
SCL_EXT: R30.1 U6.9 U7.12 | length 10.1
  Top Layer w0.152: v1(45.241,46.797) U6.9@45.978,46.797 ; R30.1@51.214,46.756 v1(51.865,46.756) 51.865,46.431 52.668,45.628 U7.12@53.275,45.628
  Bottom Layer w0.152: v1(45.241,46.797) 45.282,46.756 v1(51.865,46.756)
SDA_EXT: R29.1 U6.13 U7.13 | length 10.1
  Top Layer w0.152: v1(45.241,44.835) U6.13@46.206,44.835 ; R29.1@51.214,45.867 v1(51.214,45.206) 51.417,45.003 U7.13@53.5,45.003
  Bottom Layer w0.152: v1(45.241,44.835) 50.843,44.835 v1(51.214,45.206)
SH_GND_DETECT: P20.8 P24.8 U2.62 | length 18.2
  Top Layer w0.152: U2.62@32.824,35.505 32.824,36.254 31.877,37.201 31.877,38.479 32.639,39.241 32.639,41.864 33.462,42.687 35.611,42.687 36.576,43.652 P20.8@36.576,44.245 v1(36.576,45.71) P20.8@36.576,47.175
  Bottom Layer w0.152: P24.8@36.576,44.245 v1(36.576,45.71) P24.8@36.576,47.175
SH_RESET: P20.7 P24.7 U2.63 | length 15.9
  Top Layer w0.152: U2.63@32.324,35.505 32.324,36.323 31.572,37.075 31.572,38.605 32.334,39.367 32.334,41.991 34.036,43.693 P20.7@34.036,44.245 v1(34.036,45.71) P20.7@34.036,47.175
  Bottom Layer w0.152: P24.7@34.036,44.245 v1(34.036,45.71) P24.7@34.036,47.175
SH_SWDCLK: P20.5 P24.5 U2.65 | length 15.6
  Top Layer w0.152: P20.5@28.956,47.175 v1(28.956,45.71) 28.956,43.094 31.267,40.782 31.267,36.517 31.324,36.46 U2.65@31.324,35.505
  Bottom Layer w0.152: P24.5@28.956,44.245 P24.5@28.956,47.175
SH_SWDIO: P20.4 P24.4 U2.66 | length 17.4
  Top Layer w0.152: P20.4@26.416,44.245 26.416,43.66 27.53,42.546 29.072,42.546 30.963,40.655 30.963,39.32 30.824,39.182 U2.66@30.824,35.505 ; P20.4@26.416,44.338 v1(26.416,45.71) P20.4@26.416,47.175
  Bottom Layer w0.152: P24.4@26.416,44.245 P24.4@26.416,47.175
SH_SWO: P20.6 P24.6 U2.21 | length 32.4
  Top Layer w0.152: P20.6@31.496,47.175 v1(31.496,45.71) P20.6@31.496,44.245 31.496,42.902 31.801,42.597 v1(31.801,39.8) ; v1(31.674,34.204) 32.715,33.162 32.715,31.485 35.763,28.437 35.763,22.189 36.324,21.628 U2.21@36.324,20.355
  Bottom Layer w0.152: P24.6@31.496,44.245 v1(31.496,45.71) P24.6@31.496,47.175 ; v1(31.674,34.204) 30.963,34.915 30.963,38.962 v1(31.801,39.8)
SH_VTG: P20.3 P24.3 Q2.4 R9.1 | length 27.1
  Top Layer w0.152: v1(23.876,45.71) P20.3@23.876,47.175
  Top Layer w0.254: P20.3@23.876,44.245 P20.3@23.876,47.175 23.876,47.752 24.689,48.565 40.317,48.565 R9.1@41.072,47.81 41.277,47.604 Q2.4@42.332,47.604
  Bottom Layer w0.254: P24.3@23.876,44.245 P24.3@23.876,47.175
SHIELD_DETECT: R39.1 SB19.2 TP15.1 U4.2 U5.2 U6.2 | length 132.9
  Top Layer w0.152: v1(46.902,45.997) U6.2@47.628,45.997 ; TP15.1@52.07,24.12 52.076,24.114 v1(52.984,24.114) v1@52.984,24.141 ; v1(63.475,37.389) 63.467,37.397 R39.1@63.467,38.075 64.237,38.075 64.465,37.846 67.574,37.846 SB19.2@68.692,38.964 ; v1(71.018,14.986) 71.577,14.986 72.136,15.545 82.389,15.545 82.995,14.938 U4.2@82.995,14.338 ; v1(91.491,50.267) 91.719,50.038 92.872,50.038 U5.2@92.876,50.035
  Mid-Layer 2 w0.152: v1(52.984,24.114) 52.984,22.302 56.076,19.21 66.168,19.21 70.392,14.986 v1(71.018,14.986) ; v1(56.21,35.865) 61.951,35.865 v1(63.475,37.389) ; v1(66.192,47.955) 68.275,50.038 91.262,50.038 v1(91.491,50.267)
  Bottom Layer w0.152: v1(46.902,45.997) 51.951,45.997 52.576,46.622 52.576,48.237 53.564,49.225 57.693,49.225 58.725,48.193 58.725,40.897 56.433,38.605 56.433,36.087 v1(56.21,35.865) 55.982,35.636 55.982,28.981 55.067,28.067 55.067,25.611 53.571,24.114 v1(52.984,24.114) ; v1(63.475,37.389) 63.297,37.567 63.297,44.331 66.167,47.201 66.167,47.93 v1(66.192,47.955)
SWDCLK: P18.4 SB21.2 U1.25 | length 38
  Top Layer w0.152: v1(62.535,17.278) P18.4@62.535,18.872 ; v1(85.623,29.134) U1.25@85.623,30.023
  Mid-Layer 2 w0.152: v1(73.355,22.25) 73.355,22.852 75.116,24.613 84.456,24.613 86.081,26.237 86.081,27.127 85.623,27.584 v1(85.623,29.134)
  Bottom Layer w0.152: SB21.2@60.872,16.35 61.168,16.35 62.096,17.278 v1(62.535,17.278) 63.062,17.805 72.72,17.805 74.041,19.126 74.041,21.565 v1(73.355,22.25)
SWDIO: P18.2 SB20.2 U1.26 | length 37.3
  Top Layer w0.152: v1(63.805,17.272) P18.2@63.805,18.872 ; U1.26@85.46,30.411 85.75,30.411 86.157,30.004 v1(86.157,28.576)
  Mid-Layer 2 w0.152: v1(74.117,22.25) 74.117,23.157 75.268,24.308 84.583,24.308 86.385,26.11 86.385,27.253 86.157,27.482 v1(86.157,28.576)
  Bottom Layer w0.152: SB20.2@62.331,16.35 62.883,16.35 v1(63.805,17.272) 64.033,17.501 72.846,17.501 74.346,19 74.346,22.022 v1(74.117,22.25)
TCKOUT: R16.1 U2.14 U2.23 | length 8.4
  Top Layer w0.152: 32.824,19.227 U2.14@32.824,20.355 v1(32.824,21.726) ; v1(37.32,21.726) 37.32,20.367 37.328,20.359 U2.23@37.324,20.355
  Bottom Layer w0.152: v1(32.824,21.726) v1(37.32,21.726)
TMSOUT: R15.1 U2.17 | length 1.4
  Top Layer w0.152: R15.1@34.324,18.915 U2.17@34.324,20.355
